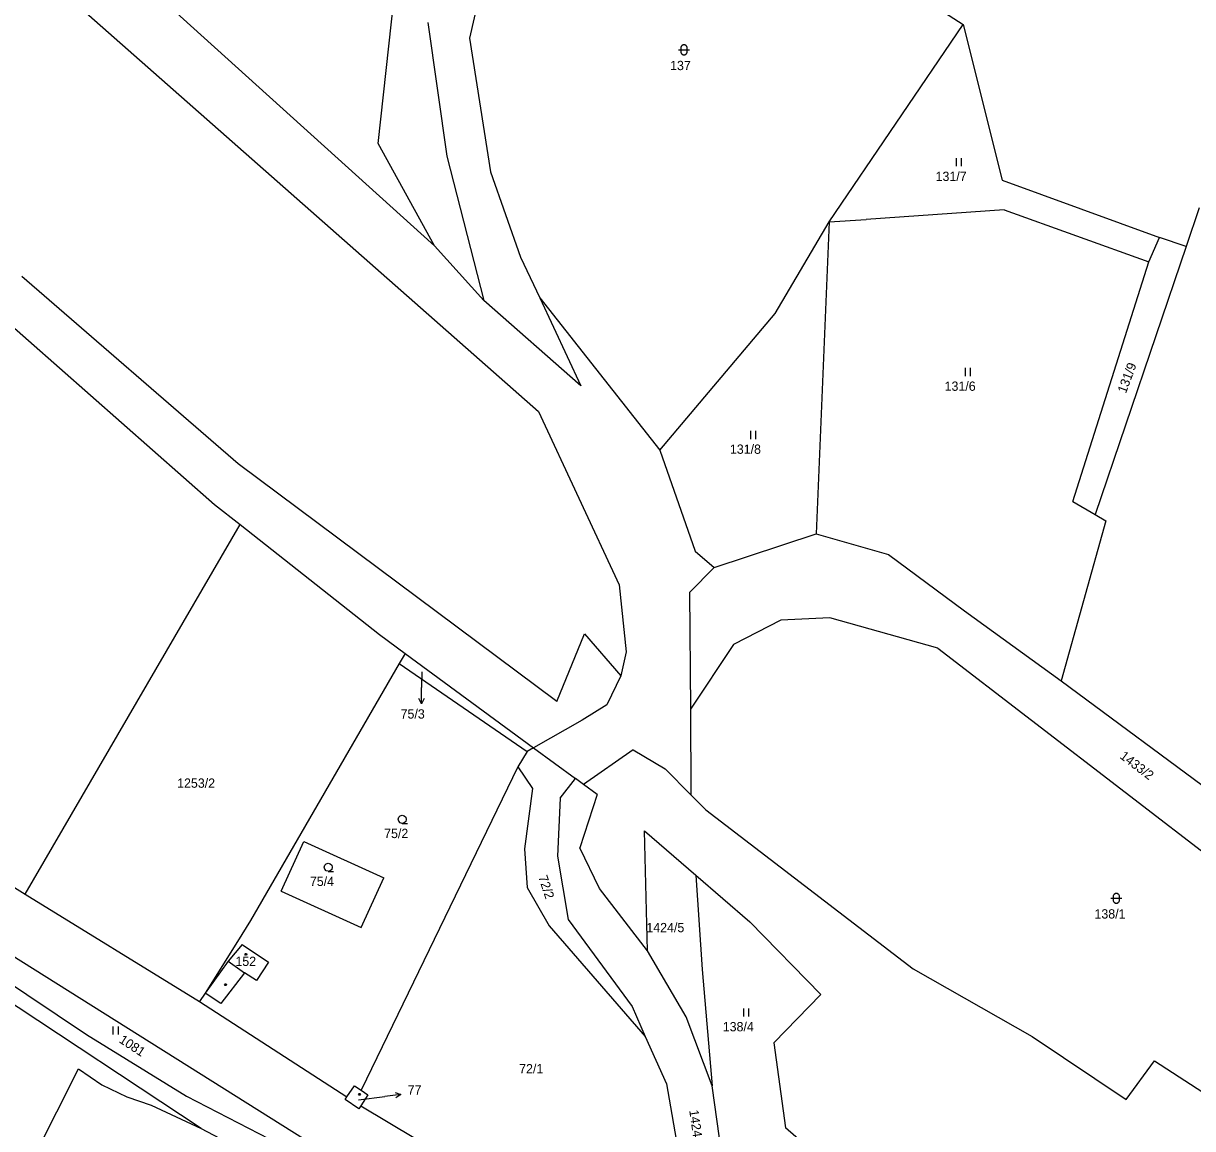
# Model space of a CAD drawing. Extents: x -852001 to -842497, y -1063614 to -1052182.
# Drawn here: x -849412.3 to -849198.1, y -1056094.9 to -1055892.4 of the extents above; entities that cross this region are included whole.
import ezdxf

# ---------------------------------------------------------------- set-up
doc = ezdxf.new("R2010")
doc.units = 0
for name, color, linetype in [('Default', 7, 'Continuous'), ('KN_HRANICE', 7, 'Continuous'), ('KN_KULTURY', 7, 'Continuous'), ('KN_PARCELY', 7, 'Continuous'), ('KN_SLUCKY', 7, 'Continuous')]:
    doc.layers.add(name, color=color, linetype=linetype)

# ---------------------------------------------------------------- blocks, each defined once
blk = doc.blocks.new('304')
at = {"layer": 'Default'}
blk.add_lwpolyline([(0, 0), (-0.38, 0.1), (-0.65, 0.37), (-0.75, 0.74), (-0.65, 1.11), (-0.38, 1.38), (-0.01, 1.48), (0.36, 1.38), (0.63, 1.11), (0.73, 0.73), (0.63, 0.35), (0.36, 0.08), (-0.02, -0.02), (0.98, -0.02)], dxfattribs=at)
blk = doc.blocks.new('306')
at = {"layer": 'Default'}
for p, q in [((-0.5, 1.5), (-0.5, 0)), ((0.5, 0), (0.5, 1.5))]:
    blk.add_line(p, q, dxfattribs=at)
blk = doc.blocks.new('316')
at = {"layer": 'Default'}
for points in [[(-1, 1), (0.27, 1), (1, 1)], [(-0.5, 1.5), (-0.4, 1.79), (-0.15, 1.97), (0.16, 1.97), (0.41, 1.79), (0.51, 1.5), (0.51, 0.5), (0.41, 0.21), (0.16, 0.03), (-0.15, 0.03), (-0.4, 0.21), (-0.5, 0.5), (-0.5, 1.5)]]:
    blk.add_lwpolyline(points, dxfattribs=at)
blk = doc.blocks.new('10292')
at = {"layer": 'Default'}
blk.add_line((0, 3), (0, 0), dxfattribs=at)
blk.add_lwpolyline([(-0.5, 2), (0, 3), (0.5, 2)], dxfattribs=at)
blk = doc.blocks.new('402')
at = {"layer": 'Default'}
blk.add_lwpolyline([(0.09, 0.15), (0.18, 0), (0.09, -0.15), (-0.09, -0.15), (-0.18, 0), (-0.09, 0.15), (0.09, 0.15)], dxfattribs=at)

msp = doc.modelspace()

# ---------------------------------------------------------------- linework, layer by layer
at = {"layer": 'KN_HRANICE'}
for p, q in [((-849300.5, -1055853.81), (-849240.11, -1055892.59)), ((-849300.5, -1055853.81), (-849240.11, -1055892.59)), ((-849347.35, -1055914.44), (-849341.76, -1055863.74)), ((-849347.35, -1055914.44), (-849341.76, -1055863.74)), ((-849405.22, -1055871.56), (-849336.98, -1055933.15)), ((-849405.22, -1055871.56), (-849336.98, -1055933.15)), ((-849326.67, -1055878.13), (-849330.6, -1055895.11)), ((-849326.67, -1055878.13), (-849330.6, -1055895.11)), ((-849411.46, -1055881.02), (-849317.98, -1055963.52)), ((-849411.46, -1055881.02), (-849317.98, -1055963.52)), ((-849338.26, -1055892.24), (-849334.75, -1055916.72)), ((-849338.26, -1055892.24), (-849334.75, -1055916.72)), ((-849264.68, -1055928.78), (-849240.11, -1055892.59)), ((-849264.68, -1055928.78), (-849240.11, -1055892.59)), ((-849240.11, -1055892.59), (-849233.02, -1055921.14)), ((-849240.11, -1055892.59), (-849233.02, -1055921.14)), ((-849330.6, -1055895.11), (-849326.77, -1055919.61)), ((-849330.6, -1055895.11), (-849326.77, -1055919.61)), ((-849336.98, -1055933.15), (-849347.35, -1055914.44)), ((-849336.98, -1055933.15), (-849347.35, -1055914.44)), ((-849334.75, -1055916.72), (-849327.97, -1055943.22)), ((-849334.75, -1055916.72), (-849327.97, -1055943.22)), ((-849326.77, -1055919.61), (-849321.28, -1055935.24)), ((-849326.77, -1055919.61), (-849321.28, -1055935.24)), ((-849233.02, -1055921.14), (-849204.15, -1055931.66)), ((-849233.02, -1055921.14), (-849204.15, -1055931.66)), ((-849439.03, -1055926.18), (-849377.32, -1055980.55)), ((-849439.03, -1055926.18), (-849377.32, -1055980.55)), ((-849232.6, -1055926.58), (-849257.89, -1055928.33)), ((-849232.6, -1055926.58), (-849257.89, -1055928.33)), ((-849232.6, -1055926.58), (-849206.11, -1055936.08)), ((-849232.6, -1055926.58), (-849206.11, -1055936.08)), ((-849196.89, -1055926.22), (-849199.3, -1055933.32)), ((-849196.89, -1055926.22), (-849199.3, -1055933.32)), ((-849274.6, -1055945.56), (-849264.68, -1055928.78)), ((-849274.6, -1055945.56), (-849264.68, -1055928.78)), ((-849264.68, -1055928.78), (-849267.09, -1055985.92)), ((-849264.68, -1055928.78), (-849267.09, -1055985.92)), ((-849264.68, -1055928.78), (-849257.89, -1055928.33)), ((-849264.68, -1055928.78), (-849257.89, -1055928.33)), ((-849206.11, -1055936.08), (-849204.15, -1055931.66)), ((-849206.11, -1055936.08), (-849204.15, -1055931.66)), ((-849199.3, -1055933.32), (-849204.15, -1055931.66)), ((-849199.3, -1055933.32), (-849204.15, -1055931.66)), ((-849336.98, -1055933.15), (-849327.97, -1055943.22)), ((-849336.98, -1055933.15), (-849327.97, -1055943.22)), ((-849199.3, -1055933.32), (-849215.96, -1055982.42)), ((-849199.3, -1055933.32), (-849215.96, -1055982.42)), ((-849321.28, -1055935.24), (-849317.68, -1055942.69)), ((-849321.28, -1055935.24), (-849317.68, -1055942.69)), ((-849220.04, -1055980.03), (-849206.11, -1055936.08)), ((-849220.04, -1055980.03), (-849206.11, -1055936.08)), ((-849372.97, -1055973.13), (-849412.64, -1055938.82)), ((-849372.97, -1055973.13), (-849412.64, -1055938.82)), ((-849317.68, -1055942.69), (-849295.72, -1055970.63)), ((-849317.68, -1055942.69), (-849310.2, -1055958.82)), ((-849317.68, -1055942.69), (-849295.72, -1055970.63)), ((-849317.68, -1055942.69), (-849310.2, -1055958.82)), ((-849310.2, -1055958.82), (-849327.97, -1055943.22)), ((-849310.2, -1055958.82), (-849327.97, -1055943.22)), ((-849295.72, -1055970.63), (-849274.6, -1055945.56)), ((-849295.72, -1055970.63), (-849274.6, -1055945.56)), ((-849567.55, -1055954.51), (-849412.04, -1056051.96)), ((-849567.55, -1055954.51), (-849412.04, -1056051.96)), ((-849317.98, -1055963.52), (-849303.18, -1055995.29)), ((-849317.98, -1055963.52), (-849303.18, -1055995.29)), ((-849295.72, -1055970.63), (-849289.26, -1055989.1)), ((-849295.72, -1055970.63), (-849289.26, -1055989.1)), ((-849314.59, -1056016.66), (-849372.97, -1055973.13)), ((-849314.59, -1056016.66), (-849372.97, -1055973.13)), ((-849377.32, -1055980.55), (-849372.63, -1055984.26)), ((-849377.32, -1055980.55), (-849372.63, -1055984.26)), ((-849220.04, -1055980.03), (-849215.96, -1055982.42)), ((-849220.04, -1055980.03), (-849215.96, -1055982.42)), ((-849213.99, -1055983.55), (-849222.2, -1056012.85)), ((-849213.99, -1055983.55), (-849222.2, -1056012.85)), ((-849215.96, -1055982.42), (-849213.99, -1055983.55)), ((-849215.96, -1055982.42), (-849213.99, -1055983.55)), ((-849412.04, -1056051.96), (-849372.63, -1055984.26)), ((-849412.04, -1056051.96), (-849372.63, -1055984.26)), ((-849372.63, -1055984.26), (-849347.1, -1056004.38)), ((-849372.63, -1055984.26), (-849347.1, -1056004.38)), ((-849285.77, -1055992.1), (-849267.09, -1055985.92)), ((-849285.77, -1055992.1), (-849267.09, -1055985.92)), ((-849267.09, -1055985.92), (-849253.79, -1055989.76)), ((-849267.09, -1055985.92), (-849253.79, -1055989.76)), ((-849289.26, -1055989.1), (-849285.77, -1055992.1)), ((-849289.26, -1055989.1), (-849285.77, -1055992.1)), ((-849253.79, -1055989.76), (-849239.89, -1056000.07)), ((-849253.79, -1055989.76), (-849239.89, -1056000.07)), ((-849290.28, -1055996.68), (-849285.77, -1055992.1)), ((-849290.28, -1055996.68), (-849285.77, -1055992.1)), ((-849303.18, -1055995.29), (-849301.89, -1056007.54)), ((-849303.18, -1055995.29), (-849301.89, -1056007.54)), ((-849290.28, -1055996.68), (-849290.13, -1056018.07)), ((-849290.28, -1055996.68), (-849290.13, -1056018.07)), ((-849239.89, -1056000.07), (-849222.2, -1056012.85)), ((-849239.89, -1056000.07), (-849222.2, -1056012.85)), ((-849273.52, -1056001.76), (-849282.24, -1056006.2)), ((-849273.52, -1056001.76), (-849282.24, -1056006.2)), ((-849264.55, -1056001.32), (-849273.52, -1056001.76)), ((-849264.55, -1056001.32), (-849273.52, -1056001.76)), ((-849244.77, -1056006.91), (-849264.55, -1056001.32)), ((-849244.77, -1056006.91), (-849264.55, -1056001.32)), ((-849347.1, -1056004.38), (-849342.4, -1056007.84)), ((-849347.1, -1056004.38), (-849342.4, -1056007.84)), ((-849314.59, -1056016.66), (-849309.5, -1056004.28)), ((-849314.59, -1056016.66), (-849309.5, -1056004.28)), ((-849309.5, -1056004.28), (-849302.85, -1056011.99)), ((-849309.5, -1056004.28), (-849302.85, -1056011.99)), ((-849282.24, -1056006.2), (-849290.13, -1056018.07)), ((-849282.24, -1056006.2), (-849290.13, -1056018.07)), ((-849244.77, -1056006.91), (-849153.01, -1056077.46)), ((-849244.77, -1056006.91), (-849153.01, -1056077.46)), ((-849342.4, -1056007.84), (-849343.46, -1056009.68)), ((-849342.4, -1056007.84), (-849343.46, -1056009.68)), ((-849342.4, -1056007.84), (-849318.86, -1056025.14)), ((-849342.4, -1056007.84), (-849318.86, -1056025.14)), ((-849301.89, -1056007.54), (-849302.85, -1056011.99)), ((-849301.89, -1056007.54), (-849302.85, -1056011.99)), ((-849343.46, -1056009.68), (-849370.71, -1056056.79)), ((-849343.46, -1056009.68), (-849370.71, -1056056.79)), ((-849343.46, -1056009.68), (-849320.03, -1056025.8)), ((-849343.46, -1056009.68), (-849320.03, -1056025.8)), ((-849302.85, -1056011.99), (-849305.41, -1056017.28)), ((-849302.85, -1056011.99), (-849305.41, -1056017.28)), ((-849222.2, -1056012.85), (-849190.94, -1056036.05)), ((-849222.2, -1056012.85), (-849190.94, -1056036.05)), ((-849305.41, -1056017.28), (-849309.97, -1056020.1)), ((-849305.41, -1056017.28), (-849309.97, -1056020.1)), ((-849290.13, -1056018.07), (-849290.02, -1056033.76)), ((-849290.13, -1056018.07), (-849290.02, -1056033.76)), ((-849309.97, -1056020.1), (-849318.86, -1056025.14)), ((-849309.97, -1056020.1), (-849318.86, -1056025.14)), ((-849320.03, -1056025.8), (-849321.71, -1056028.65)), ((-849320.03, -1056025.8), (-849321.71, -1056028.65)), ((-849318.86, -1056025.14), (-849320.03, -1056025.8)), ((-849318.86, -1056025.14), (-849320.03, -1056025.8)), ((-849318.86, -1056025.14), (-849311.18, -1056030.79)), ((-849318.86, -1056025.14), (-849311.18, -1056030.79)), ((-849300.61, -1056025.55), (-849309.7, -1056031.87)), ((-849300.61, -1056025.55), (-849309.7, -1056031.87)), ((-849300.61, -1056025.55), (-849294.73, -1056028.98)), ((-849300.61, -1056025.55), (-849294.73, -1056028.98)), ((-849321.71, -1056028.65), (-849350.45, -1056087.91)), ((-849321.71, -1056028.65), (-849350.45, -1056087.91)), ((-849321.71, -1056028.65), (-849319.06, -1056032.6)), ((-849321.71, -1056028.65), (-849319.06, -1056032.6)), ((-849294.73, -1056028.98), (-849290.02, -1056033.76)), ((-849294.73, -1056028.98), (-849290.02, -1056033.76)), ((-849319.06, -1056032.6), (-849320.53, -1056043.64)), ((-849319.06, -1056032.6), (-849320.53, -1056043.64)), ((-849313.97, -1056034.37), (-849311.18, -1056030.79)), ((-849313.97, -1056034.37), (-849311.18, -1056030.79)), ((-849309.7, -1056031.87), (-849311.18, -1056030.79)), ((-849309.7, -1056031.87), (-849311.18, -1056030.79)), ((-849307.2, -1056033.72), (-849309.7, -1056031.87)), ((-849307.2, -1056033.72), (-849309.7, -1056031.87)), ((-849313.97, -1056034.37), (-849314.46, -1056045.03)), ((-849313.97, -1056034.37), (-849314.46, -1056045.03)), ((-849307.2, -1056033.72), (-849310.38, -1056043.49)), ((-849307.2, -1056033.72), (-849310.38, -1056043.49)), ((-849290.02, -1056033.76), (-849287.32, -1056036.5)), ((-849290.02, -1056033.76), (-849287.32, -1056036.5)), ((-849287.32, -1056036.5), (-849249.28, -1056065.66)), ((-849287.32, -1056036.5), (-849249.28, -1056065.66)), ((-849298.54, -1056040.34), (-849289.1, -1056048.49)), ((-849297.98, -1056062.33), (-849298.54, -1056040.34)), ((-849298.54, -1056040.34), (-849289.1, -1056048.49)), ((-849297.98, -1056062.33), (-849298.54, -1056040.34)), ((-849447.97, -1056042.09), (-849309.42, -1056129.11)), ((-849447.97, -1056042.09), (-849309.42, -1056129.11)), ((-849365.1, -1056051.42), (-849360.97, -1056042.31)), ((-849365.1, -1056051.42), (-849360.97, -1056042.31)), ((-849360.97, -1056042.31), (-849346.31, -1056048.96)), ((-849360.97, -1056042.31), (-849346.31, -1056048.96)), ((-849306.79, -1056050.91), (-849310.38, -1056043.49)), ((-849306.79, -1056050.91), (-849310.38, -1056043.49)), ((-849320.53, -1056043.64), (-849320, -1056050.75)), ((-849320.53, -1056043.64), (-849320, -1056050.75)), ((-849314.46, -1056045.03), (-849312.52, -1056056.62)), ((-849314.46, -1056045.03), (-849312.52, -1056056.62)), ((-849447.99, -1056046.05), (-849400.8, -1056077.65)), ((-849447.99, -1056046.05), (-849400.8, -1056077.65)), ((-849350.44, -1056058.07), (-849346.31, -1056048.96)), ((-849350.44, -1056058.07), (-849346.31, -1056048.96)), ((-849289.1, -1056048.49), (-849287.99, -1056065.79)), ((-849289.1, -1056048.49), (-849279.23, -1056057.01)), ((-849289.1, -1056048.49), (-849287.99, -1056065.79)), ((-849289.1, -1056048.49), (-849279.23, -1056057.01)), ((-849412.04, -1056051.96), (-849380.09, -1056071.64)), ((-849412.04, -1056051.96), (-849380.09, -1056071.64)), ((-849365.1, -1056051.42), (-849350.44, -1056058.07)), ((-849365.1, -1056051.42), (-849350.44, -1056058.07)), ((-849320, -1056050.75), (-849315.99, -1056057.76)), ((-849320, -1056050.75), (-849315.99, -1056057.76)), ((-849297.98, -1056062.33), (-849306.79, -1056050.91)), ((-849297.98, -1056062.33), (-849306.79, -1056050.91)), ((-849379.78, -1056094.91), (-849440.78, -1056054.56)), ((-849379.78, -1056094.91), (-849440.78, -1056054.56)), ((-849370.71, -1056056.79), (-849373.13, -1056060.63)), ((-849370.71, -1056056.79), (-849373.13, -1056060.63)), ((-849315.99, -1056057.76), (-849298.41, -1056078.07)), ((-849315.99, -1056057.76), (-849298.41, -1056078.07)), ((-849312.52, -1056056.62), (-849300.79, -1056072.57)), ((-849312.52, -1056056.62), (-849300.79, -1056072.57)), ((-849279.23, -1056057.01), (-849266.21, -1056070.35)), ((-849279.23, -1056057.01), (-849266.21, -1056070.35)), ((-849373.13, -1056060.63), (-849379.02, -1056070.11)), ((-849373.13, -1056060.63), (-849379.02, -1056070.11)), ((-849372.27, -1056061.2), (-849374.84, -1056064.26)), ((-849372.27, -1056061.2), (-849374.84, -1056064.26)), ((-849372.27, -1056061.2), (-849367.43, -1056064.42)), ((-849372.27, -1056061.2), (-849367.43, -1056064.42)), ((-849290.92, -1056074.46), (-849297.98, -1056062.33)), ((-849290.92, -1056074.46), (-849297.98, -1056062.33)), ((-849374.84, -1056064.26), (-849379.02, -1056070.11)), ((-849374.84, -1056064.26), (-849379.02, -1056070.11)), ((-849367.43, -1056064.42), (-849369.6, -1056067.76)), ((-849367.43, -1056064.42), (-849369.6, -1056067.76)), ((-849371.84, -1056066.36), (-849376.17, -1056072.03)), ((-849371.84, -1056066.36), (-849376.17, -1056072.03)), ((-849369.6, -1056067.76), (-849371.84, -1056066.36)), ((-849369.6, -1056067.76), (-849371.84, -1056066.36)), ((-849287.99, -1056065.79), (-849286.11, -1056087.07)), ((-849287.99, -1056065.79), (-849286.11, -1056087.07)), ((-849249.28, -1056065.66), (-849227.51, -1056078.03)), ((-849249.28, -1056065.66), (-849227.51, -1056078.03)), ((-849379.02, -1056070.11), (-849380.09, -1056071.64)), ((-849379.02, -1056070.11), (-849380.09, -1056071.64)), ((-849376.17, -1056072.03), (-849379.02, -1056070.11)), ((-849376.17, -1056072.03), (-849379.02, -1056070.11)), ((-849266.21, -1056070.35), (-849274.84, -1056079.2)), ((-849266.21, -1056070.35), (-849274.84, -1056079.2)), ((-849380.09, -1056071.64), (-849353.05, -1056089.1)), ((-849380.09, -1056071.64), (-849353.05, -1056089.1)), ((-849300.79, -1056072.57), (-849298.41, -1056078.07)), ((-849300.79, -1056072.57), (-849298.41, -1056078.07)), ((-849286.11, -1056087.07), (-849290.92, -1056074.46)), ((-849286.11, -1056087.07), (-849290.92, -1056074.46)), ((-849400.8, -1056077.65), (-849382.48, -1056088.99)), ((-849400.8, -1056077.65), (-849382.48, -1056088.99)), ((-849298.41, -1056078.07), (-849294.47, -1056086.71)), ((-849298.41, -1056078.07), (-849294.47, -1056086.71)), ((-849274.84, -1056079.2), (-849272.71, -1056094.76)), ((-849274.84, -1056079.2), (-849272.71, -1056094.76)), ((-849227.51, -1056078.03), (-849210.29, -1056089.59)), ((-849227.51, -1056078.03), (-849210.29, -1056089.59)), ((-849411.05, -1056101.37), (-849402.23, -1056083.97)), ((-849411.05, -1056101.37), (-849402.23, -1056083.97)), ((-849402.23, -1056083.97), (-849397.99, -1056086.9)), ((-849402.23, -1056083.97), (-849397.99, -1056086.9)), ((-849210.29, -1056089.59), (-849205.06, -1056082.5)), ((-849210.29, -1056089.59), (-849205.06, -1056082.5)), ((-849205.06, -1056082.5), (-849193.95, -1056089.69)), ((-849205.06, -1056082.5), (-849193.95, -1056089.69)), ((-849397.99, -1056086.9), (-849393.39, -1056089.1)), ((-849397.99, -1056086.9), (-849393.39, -1056089.1)), ((-849353.05, -1056089.1), (-849351.67, -1056087.07)), ((-849353.05, -1056089.1), (-849351.67, -1056087.07)), ((-849351.67, -1056087.07), (-849350.45, -1056087.91)), ((-849351.67, -1056087.07), (-849350.45, -1056087.91)), ((-849350.45, -1056087.91), (-849349.23, -1056088.76)), ((-849350.45, -1056087.91), (-849349.23, -1056088.76)), ((-849294.47, -1056086.71), (-849287.88, -1056125.38)), ((-849294.47, -1056086.71), (-849287.88, -1056125.38)), ((-849283.48, -1056106.16), (-849286.11, -1056087.07)), ((-849283.48, -1056106.16), (-849286.11, -1056087.07)), ((-849393.39, -1056089.1), (-849388.9, -1056090.64)), ((-849393.39, -1056089.1), (-849388.9, -1056090.64)), ((-849388.9, -1056090.64), (-849379.78, -1056094.91)), ((-849388.9, -1056090.64), (-849379.78, -1056094.91)), ((-849382.48, -1056088.99), (-849360.29, -1056100.39)), ((-849382.48, -1056088.99), (-849360.29, -1056100.39)), ((-849353.38, -1056089.59), (-849353.05, -1056089.1)), ((-849353.38, -1056089.59), (-849353.05, -1056089.1)), ((-849350.85, -1056091.31), (-849353.38, -1056089.59)), ((-849350.85, -1056091.31), (-849353.38, -1056089.59)), ((-849349.23, -1056088.76), (-849350.5, -1056090.75)), ((-849349.23, -1056088.76), (-849350.5, -1056090.75)), ((-849350.5, -1056090.75), (-849350.85, -1056091.31)), ((-849350.5, -1056090.75), (-849350.85, -1056091.31)), ((-849350.5, -1056090.75), (-849292.1, -1056125.54)), ((-849350.5, -1056090.75), (-849292.1, -1056125.54)), ((-849379.78, -1056094.91), (-849356.05, -1056107.25)), ((-849379.78, -1056094.91), (-849356.05, -1056107.25)), ((-849242.85, -1056120.56), (-849272.71, -1056094.76)), ((-849242.85, -1056120.56), (-849272.71, -1056094.76))]:
    msp.add_line(p, q, dxfattribs=at)
at = {"layer": 'KN_PARCELY'}
for p, q in [((-849339.34, -1056011.21), (-849339.37, -1056014.1)), ((-849339.34, -1056011.21), (-849339.37, -1056014.1)), ((-849350.93, -1056089.65), (-849346.14, -1056089.05)), ((-849350.93, -1056089.65), (-849346.14, -1056089.05))]:
    msp.add_line(p, q, dxfattribs=at)
at = {"layer": 'KN_SLUCKY'}
msp.add_line((-849374.84, -1056064.26), (-849371.84, -1056066.36), dxfattribs=at)
msp.add_line((-849374.84, -1056064.26), (-849371.84, -1056066.36), dxfattribs=at)

# ---------------------------------------------------------------- block references
at = {"layer": 'KN_KULTURY'}
for name, p in [('316', (-849291.29, -1055898.28)), ('316', (-849291.29, -1055898.28)), ('306', (-849240.94, -1055918.59)), ('306', (-849240.94, -1055918.59)), ('306', (-849239.29, -1055957.04)), ('306', (-849239.29, -1055957.04)), ('306', (-849278.63, -1055968.58)), ('306', (-849278.63, -1055968.58)), ('304', (-849342.92, -1056038.99)), ('304', (-849342.92, -1056038.99)), ('304', (-849356.48, -1056047.77)), ('304', (-849356.48, -1056047.77)), ('316', (-849212.07, -1056053.73)), ('316', (-849212.07, -1056053.73)), ('402', (-849371.56, -1056062.98)), ('402', (-849371.56, -1056062.98)), ('402', (-849375.28, -1056068.54)), ('402', (-849375.28, -1056068.54)), ('306', (-849279.9, -1056074.4)), ('306', (-849279.9, -1056074.4)), ('306', (-849395.44, -1056077.71)), ('306', (-849395.44, -1056077.71)), ('402', (-849350.75, -1056088.62)), ('402', (-849350.75, -1056088.62))]:
    msp.add_blockref(name, p, dxfattribs=at)
at = {"layer": 'KN_PARCELY'}
for p, rotation in [((-849339.37, -1056014.1), 179.33579), ((-849339.37, -1056014.1), 179.33579), ((-849346.14, -1056089.05), -82.86031400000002), ((-849346.14, -1056089.05), -82.86031400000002)]:
    msp.add_blockref('10292', p, dxfattribs=dict(at, rotation=rotation))

# ---------------------------------------------------------------- texts
for s, height, p in [('137', 1.7, (-849293.84, -1055900.98)), ('137', 1.7, (-849293.84, -1055900.98)), ('131/7', 1.7, (-849245.19, -1055921.29)), ('131/7', 1.7, (-849245.19, -1055921.29)), ('131/6', 1.7, (-849243.54, -1055959.74)), ('131/6', 1.7, (-849243.54, -1055959.74)), ('131/8', 1.7, (-849282.88, -1055971.28)), ('131/8', 1.7, (-849282.88, -1055971.28)), ('75/3', 0.1, (-849339.54, -1056011.21)), ('75/3', 0.1, (-849339.54, -1056011.21)), ('75/3', 1.7, (-849343.22, -1056019.79)), ('75/3', 1.7, (-849343.22, -1056019.79)), ('1253/2', 1.7, (-849384.17, -1056032.47)), ('1253/2', 1.7, (-849384.17, -1056032.47)), ('75/2', 1.7, (-849346.24, -1056041.69)), ('75/2', 1.7, (-849346.24, -1056041.69)), ('75/4', 1.7, (-849359.84, -1056050.47)), ('75/4', 1.7, (-849359.84, -1056050.47)), ('138/1', 1.7, (-849216.08, -1056056.43)), ('138/1', 1.7, (-849216.08, -1056056.43)), ('1424/5', 1.7, (-849298.19, -1056058.94)), ('1424/5', 1.7, (-849298.19, -1056058.94)), ('152', 1.7, (-849373.49, -1056065.12)), ('152', 1.7, (-849373.49, -1056065.12)), ('138/4', 1.7, (-849284.19, -1056077.1)), ('138/4', 1.7, (-849284.19, -1056077.1)), ('72/1', 1.7, (-849321.5, -1056084.8)), ('72/1', 1.7, (-849321.5, -1056084.8)), ('77', 1.7, (-849341.92, -1056088.68)), ('77', 1.7, (-849341.92, -1056088.68)), ('77', 0.1, (-849351.03, -1056089.65)), ('77', 0.1, (-849351.03, -1056089.65))]:
    msp.add_text(s, height=height, dxfattribs=at).set_placement(p)
for s, rotation, p in [('131/9', 69.614, (-849210.32, -1055960.31)), ('131/9', 69.614, (-849210.32, -1055960.31)), ('1433/2', 322.747, (-849211.57, -1056026.95)), ('1433/2', 322.747, (-849211.57, -1056026.95)), ('72/2', 288.484, (-849318.02, -1056048.82)), ('72/2', 288.484, (-849318.02, -1056048.82)), ('1081', 326.758, (-849394.95, -1056079.04)), ('1081', 326.758, (-849394.95, -1056079.04)), ('1424/4', 278.228, (-849290.34, -1056091.59)), ('1424/4', 278.228, (-849290.34, -1056091.59))]:
    msp.add_text(s, height=1.7, rotation=rotation, dxfattribs=at).set_placement(p)

doc.saveas('drawing.dxf')
